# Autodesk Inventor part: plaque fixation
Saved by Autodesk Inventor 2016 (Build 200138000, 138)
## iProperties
Created: 2013-10
Part Number: plaque fixation
Material: solidworks materials|Acier allié inoxydable
Document SubType Name: Modeling
Designer: Bruno
Density: 7.3 g/cm^3
Appearance: 198,193,188
Author: Bruno
Sending System: SolidWorks 2013
Last Author: christophe
Last Saved: 2014-02-15
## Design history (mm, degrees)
feature "Symétrie1"
node "Solide1"
